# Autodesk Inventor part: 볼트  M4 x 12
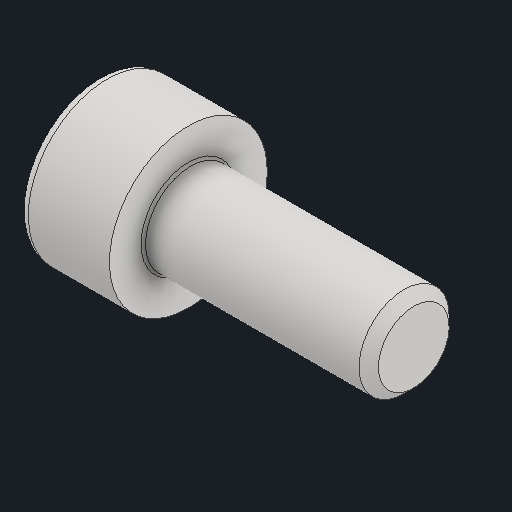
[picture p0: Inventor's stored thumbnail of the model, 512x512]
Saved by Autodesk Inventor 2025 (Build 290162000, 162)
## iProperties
Created: 2025-08
Part Number: 볼트  M4 x 12
Material: 스테인리스강
Description: 6각머리 태핑 나사
Document SubType Name: Modeling
Designer: infra012
Density: 8.08 g/cm^3
Appearance: 기본값
Author: jhkim
Sending System: Autodesk Inventor 2026
Preprocessor: ST-DEVELOPER v20.1
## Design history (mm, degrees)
sketch "스케치1"
  geometry: 1 further point
  constraints: 1 other
feature "Solid1"
node "솔리드1"
